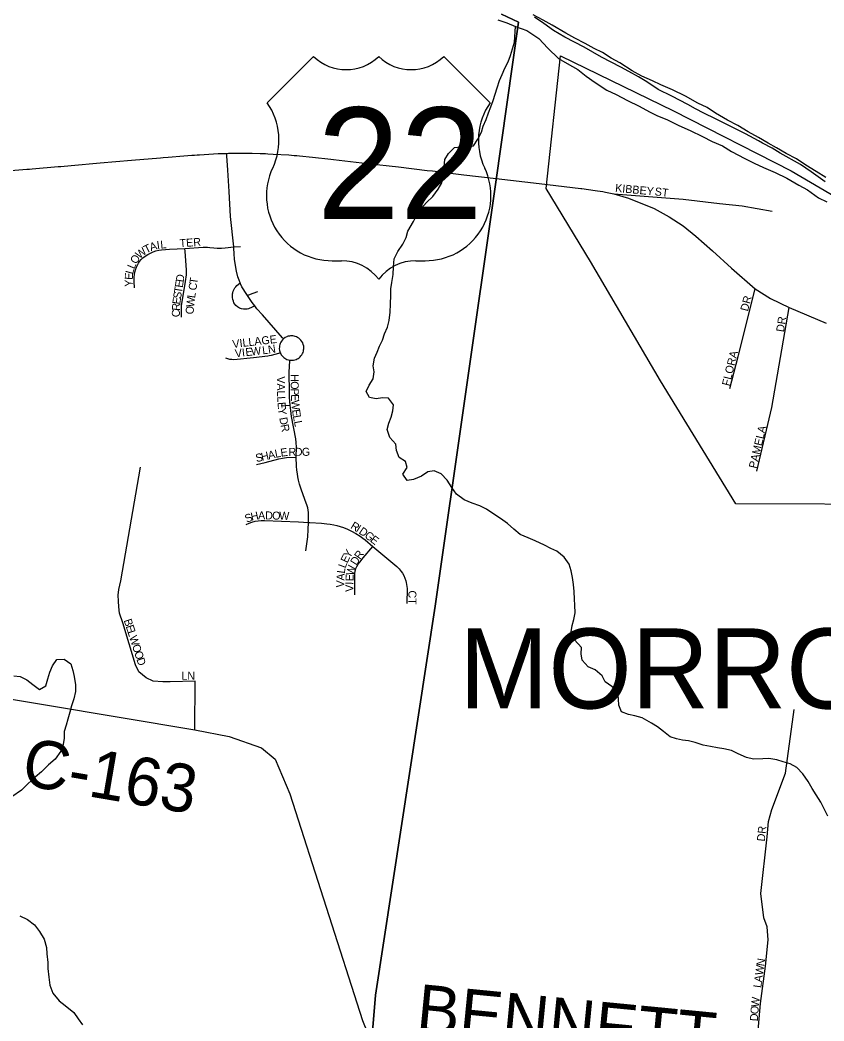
# Model space of a CAD drawing. Extents: x 1310247 to 1664935, y 284496 to 704931.
# Drawn here: x 1499349 to 1504369, y 493662 to 499915 of the extents above; entities that cross this region are included whole.
import ezdxf

# ---------------------------------------------------------------- set-up
doc = ezdxf.new("R2010")
doc.units = 0
for name, color, linetype in [('GM_P_State_Location', 7, 'Continuous'), ('GM_P_State_Shield', 7, 'Continuous'), ('GM_X_Adjacent_County', 7, 'Continuous'), ('GM_X_Airport_Class_3', 7, 'Continuous'), ('GM_X_City_Street', 7, 'Continuous'), ('GM_X_Corporation', 7, 'Continuous'), ('GM_X_Corporation_Text', 7, 'Continuous'), ('GM_X_County', 7, 'Continuous'), ('GM_X_County_Road_Text', 7, 'Continuous'), ('GM_X_Interchange_Ramps', 7, 'Continuous'), ('GM_X_Major_Lake_Text', 7, 'Continuous'), ('GM_X_Minor_River_Text', 7, 'Continuous'), ('GM_X_Rail_Line', 7, 'Continuous'), ('GM_X_State_Location', 7, 'Continuous'), ('GM_X_Township_Road', 7, 'Continuous'), ('GM_X_Township_Subdivision', 7, 'Continuous')]:
    doc.layers.add(name, color=color, linetype=linetype)

msp = doc.modelspace()

# ---------------------------------------------------------------- linework, layer by layer
at = {"layer": 'GM_P_State_Shield'}
for points in [[(1499212.7, 498968.2), (1499392.5, 498982.7), (1499408.9, 498984.1), (1499425.2, 498985.4), (1499588.6, 498999.4), (1499605, 499000.8), (1499669.4, 499006.4), (1499850.1, 499022.1), (1500046.2, 499038.5), (1500225.9, 499053.8), (1500242.2, 499055.3), (1500274.9, 499058.1), (1500372.9, 499066.1), (1500422, 499069.8), (1500438.4, 499071), (1500454.7, 499072.2), (1500471.1, 499073.3), (1500585.7, 499080), (1500623.5, 499081.3), (1500635, 499081.7), (1500640.4, 499081.9), (1500651.4, 499082.1), (1500667.8, 499082.4), (1500684.2, 499082.6), (1500799.2, 499082.4), (1500848.4, 499081.3), (1500864.8, 499080.8), (1500881.2, 499080.2), (1500897.6, 499079.6), (1500929.2, 499077.7), (1501028.8, 499071.7), (1501045.1, 499070.5), (1501061.5, 499069.1), (1501077.9, 499067.7), (1501094.2, 499066.3), (1501175.9, 499058.6), (1501290.1, 499046.3), (1501306.4, 499044.4), (1501518.2, 499019.3), (1501713.6, 498996.8), (1501892.5, 498975.8), (1501925.1, 498972.1), (1501941.4, 498970.3), (1502088, 498952.6), (1502120.5, 498948.6), (1502323, 498924.6), (1502323, 498924.6), (1502591.5, 498893)], [(1502591.5, 498893), (1502850.7, 498862.5)], [(1502850.7, 498862.5), (1502858.3, 498861.6), (1502939.7, 498850.7), (1502955.9, 498848.4), (1502988.4, 498843.1), (1503004.6, 498840.1), (1503036.8, 498833.4), (1503056.5, 498828.3), (1503147.9, 498802.7), (1503310.1, 498738.4), (1503402.2, 498685.4), (1503490.5, 498628.6), (1503568.7, 498565.5), (1503672.8, 498473.4), (1503792.7, 498364.9), (1503940.3, 498236.2), (1504036.2, 498174.4), (1504152.3, 498118.9), (1504383.2, 498021.7)]]:
    msp.add_lwpolyline(points, dxfattribs=at)
at = {"layer": 'GM_X_Adjacent_County'}
for points in [[(1502355.3, 499951.8), (1502462.6, 499902.3), (1502317.7, 498887), (1501941.8, 496253.9), (1501569.8, 493822.2), (1501545.5, 493545.9), (1501324.8, 491032.1), (1501158, 489169.3), (1501048.2, 487942.5)], [(1501048.2, 487942.5), (1501158, 489169.3), (1501324.8, 491032.1), (1501545.5, 493545.9), (1501569.8, 493822.2), (1501941.8, 496253.9), (1502317.7, 498887), (1502462.6, 499902.3), (1502355.3, 499951.8)]]:
    msp.add_lwpolyline(points, dxfattribs=at)
at = {"layer": 'GM_X_Airport_Class_3'}
for p, q in [((1501182.9, 499687.6), (1500892.9, 499397.6)), ((1502285.1, 499397.6), (1501995, 499687.6)), ((1501298.9, 498411.5), (1501356.9, 498411.5)), ((1501821, 498411.5), (1501879, 498411.5))]:
    msp.add_line(p, q, dxfattribs=at)
for centre, radius, start, end in [((1501385.9, 499894.8), 290, 225.573, 314.427), ((1501792, 499894.8), 290, 225.573, 314.427), ((1500560.3, 499164.7), 406.1, 334.54712, 35.00093), ((1502617.7, 499164.7), 406.1, 144.99907, 205.45288), ((1501294.4, 498817.5), 406.1, 154.83192, 270.63826), ((1501883.5, 498817.5), 406.1, 269.36174, 25.16808), ((1501356.9, 498121.4), 290, 36.8699, 90), ((1501821, 498121.4), 290, 90, 143.1301)]:
    msp.add_arc(centre, radius, start, end, dxfattribs=at)
at = {"layer": 'GM_X_City_Street'}
for points in [[(1502878.7, 499769.1), (1502813.3, 499800.8), (1502757.9, 499832.3), (1502672.9, 499882.5), (1502615.5, 499914), (1502554.1, 499947.6)], [(1502332.5, 499915.1), (1502388.2, 499897.7), (1502443.8, 499874.2), (1502513.4, 499848.4), (1502588.4, 499798.5), (1502645.1, 499738.9), (1502711.7, 499675.1), (1502765.1, 499643.7), (1502832.4, 499605.9), (1502885.5, 499564.5), (1502940.7, 499525), (1503013.7, 499477.1), (1503071.2, 499449.6), (1503142.5, 499411.7), (1503215.9, 499375.8), (1503279.2, 499342.1), (1503330.8, 499316.8), (1503388.4, 499293.3), (1503463.7, 499255.3), (1503533.2, 499225.5)], [(1504380.7, 498931.7), (1504321.5, 498969.3), (1504256.3, 499009), (1504197.1, 499048.6), (1504133.6, 499080.2), (1504072.3, 499115.8), (1504020.9, 499145.2), (1503961.6, 499180.7), (1503896.3, 499216.5), (1503831, 499256.2), (1503767.7, 499289.8), (1503692.5, 499333.8), (1503639.2, 499369.2), (1503581.7, 499394.7), (1503504.5, 499438.7), (1503423.3, 499478.9), (1503351.8, 499510.7), (1503298.2, 499534.1), (1503232.8, 499563.8), (1503171.4, 499597.4), (1503094.4, 499647.5), (1503040.9, 499676.9), (1502985.7, 499712.3), (1502934.1, 499737.7), (1502878.7, 499769.1)], [(1503533.2, 499225.5), (1503610.5, 499187.5), (1503671.9, 499155.9), (1503735.4, 499128.3), (1503792.7, 499092.8), (1503875.9, 499050.6), (1503933.4, 499021.1), (1503990.9, 498993.6), (1504064.3, 498961.7), (1504137.7, 498927.8), (1504212.9, 498883.8), (1504266.3, 498854.4), (1504335.3, 498804.5), (1504386.8, 498779.2)]]:
    msp.add_lwpolyline(points, dxfattribs=at)
at = {"layer": 'GM_X_Corporation_Text'}
for points in [[(1503056.5, 498828.3), (1503490.5, 498795.2), (1503717.5, 498769.5)], [(1503717.5, 498769.5), (1503858.9, 498753.5), (1504045.7, 498720.7)], [(1503836.5, 497820.8), (1503940.3, 498236.2)], [(1503950.9, 497097.4), (1504042.9, 497494.4), (1504152.3, 498118.9)], [(1503782.6, 497613.6), (1503834.4, 497812.4), (1503836.5, 497820.8)]]:
    msp.add_lwpolyline(points, dxfattribs=at)
at = {"layer": 'GM_X_County'}
msp.add_lwpolyline([(1504377.5, 498904.4), (1504288.7, 498966.1), (1504223.6, 499013.3), (1504096.9, 499083.6), (1504045.5, 499114.6), (1503986.3, 499146.3), (1503960.4, 499160.2), (1503879.2, 499203.7), (1503788.1, 499249.4), (1503693, 499297.2), (1503619.7, 499332.5), (1503568.2, 499359.5), (1503518.7, 499386.4), (1503419.7, 499438.2), (1503334.6, 499481.8), (1503263.5, 499529.2), (1503212.1, 499560.1), (1503150.7, 499593.3), (1503101.2, 499620.2), (1502980.4, 499682.4), (1502871.6, 499744.5), (1502750.8, 499808.7), (1502681.6, 499850), (1502620.5, 499893.1), (1502561.2, 499932.2)], dxfattribs=at)
at = {"layer": 'GM_X_County_Road_Text'}
msp.add_lwpolyline([(1499034.7, 495715.3), (1500441.5, 495480.8), (1500656, 495438.5), (1500856.4, 495368.1), (1500942.5, 495297.6), (1501035.1, 495080), (1501487.6, 493664.7), (1501519.9, 493588.3), (1501545.5, 493545.9), (1501587.7, 493492.8), (1501641.4, 493434), (1501645.1, 493429.1)], dxfattribs=at)
at = {"layer": 'GM_X_Major_Lake_Text'}
msp.add_lwpolyline([(1504929.1, 496888.4), (1503819.6, 496892.3), (1503349.5, 497661.6), (1502912.1, 498406.5), (1502635.3, 498862.8), (1502723.9, 499691.9), (1503430.7, 499347), (1504165.2, 498973.6), (1504708.1, 498654.6)], dxfattribs=at)
at = {"layer": 'GM_X_Minor_River_Text'}
for points in [[(1502231.5, 499213.3), (1502242.2, 499251.2), (1502261, 499293), (1502273.7, 499334.9), (1502288.4, 499372.8), (1502303.1, 499412.6), (1502315.8, 499452.5), (1502328.5, 499490.4), (1502343.3, 499536.3), (1502360, 499574.1), (1502376.7, 499614), (1502397.4, 499653.7), (1502412.1, 499693.6), (1502424.9, 499735.5), (1502437.6, 499777.4), (1502443.8, 499874.2)], [(1503044, 495751.8), (1503002.4, 495780.5), (1502985, 495818.9), (1502941.5, 495855.7), (1502897.6, 495874.4), (1502860.2, 495915.1), (1502852.8, 495955.4), (1502855.5, 495995.4), (1502812.2, 496042.2), (1502788.8, 496080.7), (1502797.6, 496132.7), (1502808.3, 496170.6), (1502815, 496210.6), (1502813.8, 496258.7), (1502812.4, 496296.8), (1502809.2, 496345), (1502806, 496389.2), (1502798.7, 496431.4), (1502791.3, 496473.6), (1502778, 496515.9), (1502746.6, 496558.5), (1502701.1, 496597.4), (1502663.3, 496614), (1502623.5, 496634.7), (1502565.8, 496661.7), (1502522, 496680.4), (1502472.2, 496701.2), (1502432.6, 496734), (1502393.1, 496768.7), (1502349.5, 496801.5), (1502307.8, 496828.2), (1502262.2, 496859), (1502220.4, 496879.7), (1502172.5, 496896.5), (1502122.7, 496917.3), (1502075.2, 496952.2), (1502045.8, 496994.8), (1502016.5, 497041.3), (1501979, 497080), (1501935.2, 497098.8), (1501894.9, 497091.4), (1501856.4, 497066), (1501805.9, 497044.7), (1501767.6, 497037.3), (1501740.2, 497077.8), (1501767, 497119.5), (1501755.6, 497157.8), (1501715.9, 497182.5), (1501700.6, 497224.8), (1501695.2, 497265), (1501657.8, 497307.7), (1501642.6, 497356.1), (1501651.3, 497396), (1501666, 497433.9), (1501676.7, 497473.8), (1501681.3, 497511.8), (1501649.9, 497552.4), (1501611.8, 497555), (1501573.6, 497547.6), (1501531.6, 497556.3), (1501510.2, 497594.8), (1501528.9, 497634.6), (1501553.7, 497674.3), (1501560.4, 497716.3), (1501555, 497754.5), (1501561.8, 497802.5), (1501578.5, 497840.3), (1501593.2, 497878.1), (1501611.9, 497915.9), (1501624.6, 497953.8), (1501643.3, 497995.6), (1501654.1, 498037.6), (1501661, 498089.6), (1501661.8, 498139.7), (1501664.7, 498195.8), (1501665.4, 498235.9), (1501672.1, 498275.9), (1501679, 498325.9), (1501681.8, 498372), (1501686.6, 498424), (1501707.5, 498469.8), (1501740.3, 498515.4), (1501761.1, 498557.1), (1501771.8, 498595.1), (1501806.9, 498656.7), (1501827.7, 498698.4), (1501854.4, 498738.1), (1501887.1, 498775.7), (1501927.9, 498813.1), (1501960.8, 498858.7), (1501983.5, 498898.5), (1501994.3, 498946.4), (1501997.2, 498998.5), (1502002, 499042.5), (1502024.7, 499080.2), (1502063.4, 499117.7), (1502101.6, 499123.1), (1502139.7, 499120.5), (1502180, 499129.9), (1502208.8, 499171.5), (1502231.5, 499213.3)], [(1499311.7, 495817.3), (1499349.8, 495814.7), (1499391.5, 495792), (1499429.1, 495763.3), (1499470.8, 495732.6), (1499511.3, 495756), (1499524, 495799.9), (1499534.8, 495841.8), (1499551.5, 495879.7), (1499580.2, 495919.3), (1499624.4, 495922.6), (1499666, 495893.9), (1499679.4, 495851.6), (1499686.8, 495813.4), (1499695.9, 495761.1), (1499695.2, 495721), (1499686.4, 495675), (1499671.7, 495631.1), (1499661, 495591.2), (1499648.2, 495547.3), (1499637.5, 495509.4), (1499624.8, 495469.5), (1499624.1, 495429.4), (1499619.5, 495389.4), (1499604.7, 495347.5), (1499569.8, 495297.9), (1499527, 495262.5), (1499484.2, 495219.1), (1499443.5, 495185.7), (1499398.6, 495142.3), (1499357.9, 495104.8), (1499299, 495061.7)], [(1504394.6, 494942.3), (1504369.3, 494990.8), (1504349.9, 495029.2), (1504320.6, 495073.8), (1504295.2, 495114.3), (1504269.9, 495158.8), (1504238.5, 495205.5), (1504199.1, 495246.2), (1504159.4, 495268.9), (1504115.4, 495281.6), (1504075.5, 495292.3), (1504025.5, 495301.1), (1503987.3, 495299.7), (1503929.1, 495296.6), (1503885.2, 495307.3), (1503833.4, 495330.2), (1503791.6, 495350.9), (1503743.6, 495361.7), (1503705.6, 495368.3), (1503661.6, 495377.1), (1503615.6, 495385.8), (1503565.7, 495400.6), (1503523.8, 495411.3), (1503485.8, 495416), (1503447.8, 495424.6), (1503409.9, 495437.2), (1503368.3, 495470), (1503330.7, 495498.6), (1503293, 495523.3), (1503233.3, 495556.3), (1503187.4, 495569.1), (1503149.4, 495575.7), (1503105.5, 495592.4), (1503088.2, 495634.8), (1503086.8, 495672.9), (1503081.6, 495721.1), (1503044, 495751.8)], [(1499348.7, 494319), (1499396.5, 494296.2)], [(1499396.5, 494296.2), (1499440, 494261.5), (1499471.4, 494220.8), (1499500.7, 494172.3), (1499513.9, 494121.9), (1499517.2, 494081.8), (1499522.4, 494027.5), (1499523.7, 493989.4), (1499528.8, 493935.2), (1499536, 493885), (1499553.3, 493836.6), (1499594.6, 493787.8), (1499632.2, 493759.1), (1499685.6, 493714.2), (1499713.1, 493675.6), (1499738.5, 493637.1)]]:
    msp.add_lwpolyline(points, dxfattribs=at)
at = {"layer": 'GM_X_State_Location'}
for points in [[(1500994.9, 497923.4), (1500989, 497930.1), (1500862.7, 498072.6), (1500828.5, 498111.4), (1500820.2, 498122.2), (1500814.8, 498129.2), (1500799.6, 498149.2), (1500769.6, 498193.6), (1500765.6, 498199.5), (1500735.1, 498248.7), (1500725.9, 498267.6), (1500723.8, 498273.1), (1500717.4, 498289.6), (1500710.3, 498311.5), (1500701.1, 498346.3), (1500692.6, 498393.1), (1500689, 498420.7), (1500686.2, 498454.8), (1500685.5, 498490.2), (1500685.3, 498497.6), (1500663.9, 498686.5), (1500654.7, 498844.3), (1500647.9, 498976.7), (1500641.5, 499066.7), (1500640.4, 499081.9)], [(1500064.1, 498242.5), (1500061.4, 498281.4), (1500061.3, 498292.4), (1500062.2, 498308.4), (1500064.2, 498324.1), (1500067.3, 498339.5), (1500071.5, 498354.6), (1500077, 498370.6), (1500082.7, 498384.3), (1500089, 498396.4), (1500095.7, 498406.7), (1500105.1, 498417.9), (1500116.9, 498429), (1500130.9, 498439.8), (1500147.4, 498450.6), (1500163.3, 498459.4), (1500179.9, 498466.8), (1500197.4, 498473), (1500215.6, 498477.7), (1500233, 498479.5), (1500283, 498482.6), (1500379.3, 498488), (1500493.7, 498495.9), (1500504.2, 498496.4), (1500519.8, 498495.8), (1500535.4, 498494.6), (1500559.6, 498491.8), (1500580.7, 498490.1), (1500595.7, 498489.5), (1500606.6, 498490.4), (1500630.5, 498492.7), (1500685.3, 498497.6), (1500725.2, 498500.6)], [(1500357.9, 498057.7), (1500358.7, 498129.1), (1500383, 498280.5), (1500388, 498323), (1500389, 498355), (1500380.7, 498468.5), (1500379.3, 498488)], [(1500814.8, 498129.2), (1500791.6, 498117.6), (1500783.5, 498113.8), (1500775.2, 498110.9), (1500766.8, 498108.9), (1500758.4, 498107.8), (1500744.1, 498107.8), (1500731.4, 498110.2), (1500719.7, 498115.1), (1500707.5, 498122.9), (1500697.7, 498131.4), (1500690, 498140.4), (1500685.3, 498148.4), (1500681.4, 498157.9), (1500678.5, 498168.8), (1500676.5, 498180.9), (1500675.6, 498197.4), (1500676.2, 498204.6), (1500677.3, 498211.1), (1500680.6, 498221.2), (1500686.1, 498232.6), (1500691, 498240.8), (1500696.7, 498248.6), (1500703.2, 498255.9), (1500710.5, 498262.8), (1500723.8, 498273.1)], [(1500769.6, 498193.6), (1500778.4, 498197.4), (1500804.6, 498208.7), (1500834.4, 498219.4)], [(1501035.1, 497789.6), (1501041.8, 497789), (1501049.5, 497789.1), (1501057.5, 497790), (1501065.4, 497791.8), (1501072.9, 497794.3), (1501079.6, 497797.3), (1501086.1, 497801.1), (1501092.3, 497805.4), (1501097.8, 497810.2), (1501103.6, 497816.4), (1501108.8, 497823.5), (1501113.3, 497831), (1501113.7, 497832), (1501116.7, 497838.7), (1501119, 497845.9), (1501120.5, 497853.6), (1501121.4, 497861.6), (1501121.4, 497869.5), (1501120.7, 497877.1), (1501118.3, 497887.4), (1501114.3, 497897.7), (1501108.9, 497907.4), (1501102.6, 497915.8), (1501096.8, 497921.8), (1501090.1, 497927.3), (1501082.8, 497932), (1501075.4, 497935.8), (1501068.4, 497938.4), (1501061, 497940.3), (1501053.5, 497941.6), (1501046.1, 497942.1), (1501039, 497941.9), (1501031.7, 497940.9), (1501024.4, 497939.2), (1501017.5, 497937), (1501016.2, 497936.3), (1501005.7, 497931.2), (1500994.9, 497923.4), (1500993.7, 497922.3), (1500987.9, 497916.4), (1500982.5, 497909.6), (1500978, 497902.3), (1500974.3, 497894.8), (1500971.7, 497887.2), (1500969.8, 497879.2), (1500968.7, 497871.1), (1500968.5, 497863.2), (1500970, 497850), (1500974, 497836.7), (1500977.1, 497830), (1500981, 497823.5), (1500985.4, 497817.4), (1500990.3, 497811.9), (1500996, 497806.7), (1501002.4, 497802), (1501009.3, 497797.9), (1501016.4, 497794.6), (1501025.6, 497791.5), (1501035.1, 497789.6)], [(1500633.3, 497805.4), (1500645.4, 497800.5), (1500658.1, 497797), (1500671.1, 497795.2), (1500684.2, 497794.9), (1500807.9, 497806.6), (1500897.1, 497817.6), (1500905.8, 497819.3), (1500918.9, 497822.1), (1500965.5, 497834.4), (1500974, 497836.7)], [(1501133.9, 496599), (1501141, 496642.9), (1501146, 496687.2), (1501148.9, 496731.6), (1501149.8, 496776.1), (1501151.2, 496823.2), (1501151, 496838.6), (1501149.3, 496853.8), (1501146.4, 496867.1), (1501142.3, 496880.2), (1501127, 496919.6), (1501103.9, 496983.6), (1501094.2, 497014.3), (1501087.5, 497039.8), (1501083.9, 497061), (1501081.3, 497080.1), (1501078.5, 497103.2), (1501076.8, 497127.5), (1501074.5, 497184.2), (1501074.8, 497246.4), (1501073.4, 497275.6), (1501070.6, 497297.9), (1501045.2, 497438.7), (1501040.1, 497475.1), (1501036.4, 497507.9), (1501032.5, 497557.2), (1501031.1, 497587.1), (1501030.8, 497715.6), (1501034.9, 497786.7), (1501035.1, 497789.6)], [(1500980.9, 497505.5), (1501036.4, 497507.9)], [(1500825.4, 497137.8), (1500879.3, 497150.6), (1500966.2, 497173.9), (1500988.5, 497178.4), (1501014.3, 497181.1), (1501068.9, 497183.9), (1501074.5, 497184.2)], [(1500441.5, 495480.8), (1500443, 495784.6), (1500286.4, 495779.9), (1500241, 495779.9), (1500181.4, 495784.4), (1500136.9, 495806), (1500090.7, 495842.5), (1500070.4, 495886.3), (1499992, 496149.4), (1499970.9, 496209.7), (1499967, 496248.8), (1499963.9, 496284.9), (1499962.3, 496321.6), (1499966.2, 496356.9), (1499978, 496412.5), (1500101.7, 497121.8)], [(1500761.8, 496762.4), (1500779.4, 496771.2), (1500797.7, 496778.4), (1500816.7, 496783.7), (1500836.1, 496787.1), (1500855.8, 496788.7), (1500875.5, 496788.4), (1501088.7, 496780.1), (1501119.3, 496778.6), (1501149.8, 496776.1), (1501158.3, 496775.7), (1501230.9, 496771.2), (1501265.1, 496768), (1501287, 496765.5), (1501307.9, 496761.6), (1501328.5, 496756.7), (1501348.8, 496750.8), (1501368.7, 496744.1), (1501394, 496733.9), (1501419.8, 496721.8), (1501447.2, 496706.9), (1501473.7, 496690.3), (1501490.2, 496678.5), (1501503.6, 496667.5), (1501552.4, 496626.2), (1501703.3, 496500.6), (1501717.8, 496486.3), (1501730.2, 496470.5), (1501737.5, 496458.7), (1501745.1, 496443.8), (1501752, 496427.7), (1501757.5, 496411.8), (1501760.7, 496400.1), (1501763.2, 496388.2), (1501765.1, 496376.1), (1501766.3, 496363.8), (1501765.2, 496270.8)], [(1501439.8, 496323.3), (1501439.8, 496437.9), (1501440.2, 496455.6), (1501442.8, 496472.9), (1501446.9, 496488.5), (1501452.3, 496501.9), (1501460.4, 496516), (1501470.6, 496529.1), (1501492.6, 496555.2), (1501552.4, 496626.2)], [(1503928.9, 493267.7), (1503974.1, 493771.3), (1504005.1, 494003.9), (1504020.8, 494169.4), (1504013.9, 494250.2), (1503993.4, 494306.2), (1503975, 494457.7), (1504015, 494811.4), (1504022.8, 494908.4), (1504044.4, 494982.2), (1504129.1, 495209.3), (1504183.3, 495608.5)]]:
    msp.add_lwpolyline(points, dxfattribs=at)

# ---------------------------------------------------------------- texts
at = {"layer": 'GM_P_State_Location'}
for s, rotation, p in [('TER', 4.40513, (1500347.5, 498494.7)), ('W', 39.5236, (1500095.8, 498420.7)), ('T', 26.35732, (1500137.4, 498455.5)), ('A', 17.88205, (1500167.1, 498470.4)), ('I', 8.42056, (1500206.8, 498483.4)), ('L', 5.06086, (1500227.8, 498486.5)), ('O', 58.79632, (1500075.9, 498386.4)), ('L', 66.98079, (1500063, 498355.7)), ('E', 87.67661, (1500053.3, 498291.2)), ('L', 74.62506, (1500054.2, 498323.4)), ('D', 81.26083, (1500370.4, 498275)), ('T', 81.28095, (1500455.7, 498262.1)), ('Y', 89.34421, (1500052.8, 498247.6)), ('T', 81.11259, (1500359.5, 498205.3)), ('E', 81.15339, (1500365, 498240.2)), ('C', 80.97686, (1500449.5, 498222.7)), ('E', 82.19054, (1500349.3, 498135.9)), ('S', 81.13958, (1500354.1, 498170.6)), ('W', 83.00633, (1500435.1, 498118.5)), ('L', 81.11259, (1500442, 498174.9)), ('R', 87.47352, (1500347.7, 498097.6)), ('O', 87.96706, (1500433.6, 498075.7)), ('C', 89.7814, (1500347.6, 498058.5)), ('VILLAGE', 6.63932, (1500678.7, 497865.6)), ('I', 6.34393, (1500737.6, 497812.1)), ('E', 6.35226, (1500759.5, 497814.6)), ('W', 6.33462, (1500794.4, 497818.5)), ('L', 6.56628, (1500864.6, 497826.3)), ('N', 8.78675, (1500901.6, 497830.6)), ('V', 6.35226, (1500693.9, 497807.3)), ('V', 270.02187, (1500953.6, 497689)), ('H', 270.04373, (1501039.6, 497702.2)), ('A', 270.40954, (1500953.6, 497644.6)), ('O', 270.03787, (1501039.6, 497658.2)), ('L', 271.55091, (1500953.9, 497599.5)), ('L', 273.27975, (1500954.9, 497562.7)), ('P', 271.28778, (1501039.7, 497613)), ('E', 272.84156, (1501040.5, 497576.3)), ('E', 274.66902, (1500957, 497526.2)), ('Y', 276.90305, (1500960.1, 497489)), ('W', 275.0854, (1501042.4, 497539)), ('D', 280.28181, (1500967.9, 497429.1)), ('E', 277.76199, (1501047.8, 497479.5)), ('L', 280.32333, (1501052.9, 497442.2)), ('R', 281.22842, (1500976, 497384.9)), ('L', 281.12775, (1501059.4, 497406.9)), ('E', 8.38894, (1500979.4, 497186.4)), ('R', 0.80146, (1501025.7, 497191.8)), ('D', 0.00001, (1501065.1, 497192.4)), ('G', 0.00001, (1501109.1, 497192.4)), ('S', 12.64439, (1500825.7, 497152.5)), ('H', 12.64968, (1500860, 497160.2)), ('A', 12.64968, (1500903, 497169.9)), ('L', 11.61002, (1500945.7, 497179.5)), ('S', 23.46044, (1500765.7, 496773.1)), ('H', 12.29171, (1500795.6, 496786.3)), ('A', 0.04372, (1500835.7, 496795.4)), ('D', 358.77601, (1500879.4, 496795.4)), ('O', 358.77601, (1500923.4, 496794.5)), ('W', 358.77254, (1500967.4, 496793.5)), ('R', 328.58655, (1501408.9, 496742.3)), ('I', 327.30418, (1501442.5, 496721.8)), ('D', 325.52187, (1501460.6, 496710.2)), ('G', 323.62399, (1501496.6, 496685.5)), ('E', 322.63294, (1501531.8, 496659.5)), ('Y', 57.71657, (1501407.7, 496549.3)), ('E', 64.1679, (1501393.1, 496518.9)), ('D', 58.09889, (1501450.1, 496504.2)), ('R', 54.76723, (1501472.9, 496540.9)), ('L', 81.52597, (1501376.7, 496454.9)), ('L', 69.45673, (1501381.2, 496487.1)), ('W', 76.5631, (1501432.5, 496440.7)), ('A', 87.33293, (1501374.8, 496412.3)), ('E', 87.95068, (1501431.6, 496408.1)), ('V', 87.35476, (1501372.7, 496368.4)), ('I', 89.69407, (1501431.5, 496386.5)), ('V', 89.95627, (1501431.5, 496342.6)), ('CT', 270, (1501774.4, 496351.4)), ('B', 288.02033, (1499996.4, 496164.9)), ('E', 288.02073, (1500008.7, 496127.2)), ('L', 288.02073, (1500019.5, 496093.7)), ('W', 288.01304, (1500030.4, 496060.3)), ('O', 288.02106, (1500048.1, 496005.9)), ('O', 288.02106, (1500061.7, 495964.1)), ('D', 288.02106, (1500075.4, 495922.2)), ('LN', 0.00001, (1500357, 495793.2)), ('DR', 83.9832, (1503999.6, 494781.6)), ('N', 80.2718, (1503995.4, 494001.3)), ('W', 82.32645, (1503987.8, 493945.1)), ('A', 82.61475, (1503982.2, 493901.5)), ('L', 82.631, (1503977.6, 493866.6)), ('W', 84.05522, (1503962.7, 493746.3)), ('O', 85.67979, (1503959.4, 493702.8)), ('D', 85.66833, (1503956.1, 493658.9))]:
    msp.add_text(s, height=50, rotation=rotation, dxfattribs=at).set_placement(p)
at = {"layer": 'GM_X_Airport_Class_3'}
msp.add_text('22', height=696.1, dxfattribs=at).set_placement((1501203.7, 498672.5))
at = {"layer": 'GM_X_Corporation'}
for s in ['/', '0']:
    msp.add_text(s, height=1, dxfattribs=at).set_placement((1501588.6, 499015.1))
msp.add_text('22', height=1, rotation=0.00001, dxfattribs=at).set_placement((1501382.2, 498808.1))
at = {"layer": 'GM_X_Interchange_Ramps'}
msp.add_text('MORROW', height=500, rotation=0.00001, dxfattribs=at).set_placement((1502091.8, 495614.1))
at = {"layer": 'GM_X_Rail_Line'}
for s, rotation, p in [('KIBBEY', 354.50671, (1503063.9, 498842.3)), ('ST', 352.88003, (1503310.5, 498820.3)), ('DR', 75.25417, (1503894.3, 498091.8)), ('DR', 81.02146, (1504119.1, 497963.1)), ('FLORA', 76.2624, (1503779.8, 497625.2)), ('PAMELA', 76.70477, (1503947.6, 497110.2))]:
    msp.add_text(s, height=50, rotation=rotation, dxfattribs=at).set_placement(p)
at = {"layer": 'GM_X_Township_Road'}
msp.add_text('C-163', height=300, rotation=350.31116, dxfattribs=at).set_placement((1499349.7, 495138))
at = {"layer": 'GM_X_Township_Subdivision'}
msp.add_text('BENNETT', height=300, rotation=354.43816, dxfattribs=at).set_placement((1501816.4, 493594.5))

doc.saveas('drawing.dxf')
